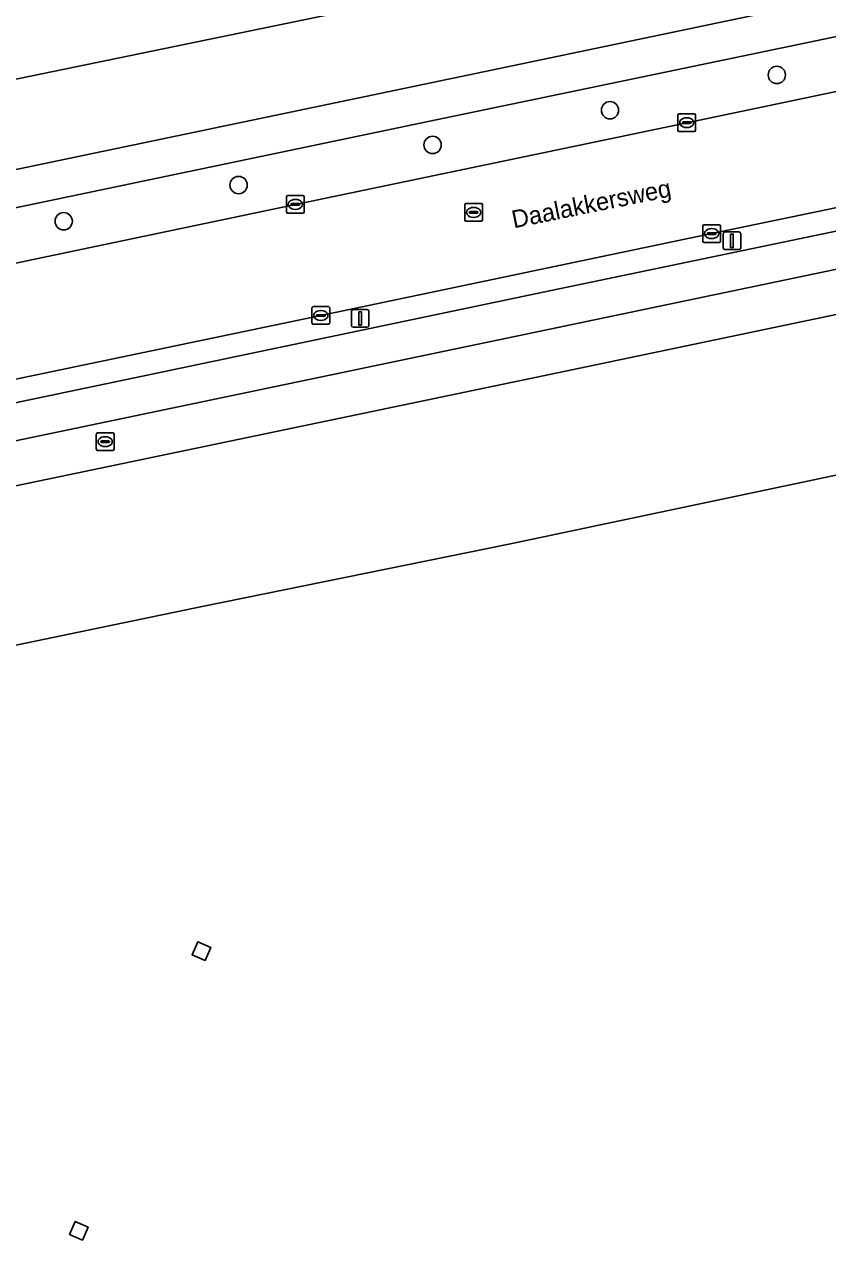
# Model space of a CAD drawing. Extents: x 164494 to 166241, y 382475 to 384495.
# Drawn here: x 165022 to 165067.4, y 384305.4 to 384374.5 of the extents above; entities that cross this region are included whole.
import ezdxf

# ---------------------------------------------------------------- set-up
doc = ezdxf.new("R2010")
doc.units = 0
for name, color, linetype in [('IMGEO_Berm_groen', 7, 'Continuous'), ('IMGEO_Boom', 7, 'Continuous'), ('IMGEO_Brandkraan', 7, 'Continuous'), ('IMGEO_Erf', 7, 'Continuous'), ('IMGEO_Fietspad_open', 7, 'Continuous'), ('IMGEO_Greppel_droge_sloot', 7, 'Continuous'), ('IMGEO_Groenvoorziening', 7, 'Continuous'), ('IMGEO_Hek', 7, 'Continuous'), ('IMGEO_Hoogspanningsmast', 7, 'Continuous'), ('IMGEO_Kolk', 7, 'Continuous'), ('IMGEO_Lichtmast', 7, 'Continuous'), ('IMGEO_Openbare_ruimte_label', 7, 'Continuous'), ('IMGEO_Rijbaan_lokaal_open', 7, 'Continuous'), ('IMGEO_Rioolput', 7, 'Continuous'), ('IMGEO_Struiken', 7, 'Continuous'), ('IMGEO_Voetpad_open', 7, 'Continuous')]:
    doc.layers.add(name, color=color, linetype=linetype)

msp = doc.modelspace()

# ---------------------------------------------------------------- linework, layer by layer
at = {"layer": 'IMGEO_Berm_groen'}
for points in [[(165103.145, 384381.247), (165078.417, 384376.067), (165044.842, 384369.066), (164998.737, 384359.434), (164936.708, 384346.52), (164925.461, 384344.192), (164926.103, 384341.106), (164933.216, 384342.574), (164954.306, 384347.035), (164980.37, 384352.43), (164994.137, 384355.385), (165015.253, 384359.737), (165037.346, 384364.383), (165059.459, 384368.999), (165082.552, 384373.828), (165103.18, 384378.131), (165103.841, 384378.298)], [(165118.108, 384374.601), (165083.93, 384367.513), (165060.866, 384362.734), (165038.786, 384358.11), (165016.662, 384353.497), (165001.186, 384350.268), (165001.461, 384348.974), (165051.79, 384359.513), (165100.699, 384369.712), (165114.768, 384372.637)]]:
    msp.add_lwpolyline(points, dxfattribs=at)
at = {"layer": 'IMGEO_Boom'}
for centre in [(165064.547, 384371.695), (165055.122, 384369.705), (165045.099, 384367.741), (165034.14, 384365.475), (165024.257, 384363.43)]:
    msp.add_circle(centre, 0.489, dxfattribs=at)
at = {"layer": 'IMGEO_Brandkraan'}
for p, q in [((165026.101, 384350.558), (165026.101, 384351.41)), ((165026.176, 384351.484), (165027.028, 384351.484)), ((165026.589, 384351.264), (165026.614, 384351.264)), ((165027.102, 384351.41), (165027.102, 384350.558)), ((165026.36, 384350.978), (165026.36, 384350.99)), ((165026.798, 384350.941), (165026.4, 384350.941)), ((165026.403, 384351.027), (165026.801, 384351.027)), ((165026.612, 384350.704), (165026.587, 384350.704)), ((165026.844, 384350.99), (165026.844, 384350.978)), ((165027.028, 384350.484), (165026.176, 384350.484))]:
    msp.add_line(p, q, dxfattribs=at)
for points in [[(165026.101, 384350.558), (165026.101, 384351.41)], [(165026.176, 384351.484), (165027.028, 384351.484)], [(165027.102, 384351.41), (165027.102, 384350.558)], [(165027.028, 384350.484), (165026.176, 384350.484)]]:
    msp.add_lwpolyline(points, dxfattribs=at)
for centre, radius, start, end in [((165026.178, 384351.408), 0.0765, 91.55205, 178.44795), ((165026.178, 384351.408), 0.0765, 91.55205, 178.44795), ((165027.026, 384351.408), 0.0765, 1.55205, 88.44795), ((165027.026, 384351.408), 0.0765, 1.55205, 88.44795), ((165026.4, 384350.987), 0.0403, 85.87752, 175.75265), ((165026.397, 384350.977), 0.0366, 178.93798, 274.71019), ((165026.801, 384350.984), 0.043, 264.86636, 352.45326), ((165026.805, 384350.989), 0.0386, 1.73085, 96.63898), ((165026.178, 384350.56), 0.0765, 181.55205, 268.44795), ((165026.178, 384350.56), 0.0765, 181.55205, 268.44795), ((165027.026, 384350.56), 0.0765, 271.55205, 358.44795), ((165027.026, 384350.56), 0.0765, 271.55205, 358.44795)]:
    msp.add_arc(centre, radius, start, end, dxfattribs=at)
for centre, major_axis, ratio, start_param, end_param in [((165026.588, 384350.984), (-0.387, 0.002), 0.722429, 4.712389, 7.853982), ((165026.613, 384350.984), (-0.39, 0.002), 0.717154, 1.570796, 4.712389)]:
    msp.add_ellipse(centre, major_axis=major_axis, ratio=ratio, start_param=start_param, end_param=end_param, dxfattribs=at)
at = {"layer": 'IMGEO_Erf'}
msp.add_lwpolyline([(165121.194, 384360.319), (165097.67, 384355.369), (165074.224, 384350.422), (165049.402, 384345.197), (165032.09, 384341.677), (165016.726, 384338.497)], dxfattribs=at)
for points in [[(165031.512, 384322.002), (165031.833, 384322.734), (165032.566, 384322.413), (165032.244, 384321.68)], [(165024.585, 384306.205), (165024.906, 384306.938), (165025.639, 384306.616), (165025.317, 384305.884)]]:
    msp.add_lwpolyline(points, close=True, dxfattribs=at)
at = {"layer": 'IMGEO_Fietspad_open'}
for points in [[(165106.766, 384384.165), (165105.349, 384383.872), (165102.387, 384383.258), (165077.784, 384378.116), (165043.832, 384371.007), (165000.08, 384361.873), (164984.803, 384358.696), (164934.915, 384348.321), (164898.89, 384340.836), (164875.602, 384335.981), (164845.275, 384329.624), (164797.88, 384319.828), (164794.806, 384319.188), (164795.6, 384317.184)], [(164795.6, 384317.184), (164798.561, 384317.801), (164845.552, 384327.536), (164876.06, 384333.902), (164900.22, 384338.981), (164917.673, 384342.602), (164918.341, 384339.504), (164926.103, 384341.106), (164925.461, 384344.192), (164936.708, 384346.52), (164998.737, 384359.434), (165044.842, 384369.066), (165078.417, 384376.067), (165103.145, 384381.247)], [(165118.509, 384373.384), (165114.768, 384372.637), (165100.699, 384369.712), (165051.79, 384359.513), (165001.461, 384348.974), (164996.183, 384347.859), (164980.371, 384344.544), (164956.926, 384339.68), (164933.359, 384334.783), (164911.059, 384330.145), (164868.55, 384321.331), (164832.678, 384313.85), (164825.97, 384312.501), (164814.364, 384310.101), (164814.35, 384310.172), (164809.331, 384309.126), (164809.333, 384309.08), (164801.696, 384307.495)], [(164802.068, 384305.407), (164809.925, 384307.04), (164833.08, 384311.822), (164838.611, 384312.969), (164868.92, 384319.253), (164912.329, 384328.255), (164932.507, 384332.46), (164958.923, 384337.938), (164978.743, 384342.085), (164996.584, 384345.814), (165001.876, 384346.919), (165052.181, 384357.436), (165101.155, 384367.679), (165118.614, 384371.278), (165123.59, 384372.323)]]:
    msp.add_lwpolyline(points, dxfattribs=at)
at = {"layer": 'IMGEO_Greppel_droge_sloot'}
msp.add_lwpolyline([(164862.281, 384339.951), (164950.027, 384358.074), (164983.603, 384364.664), (164999.896, 384367.862), (165017.437, 384370.613), (165038.566, 384374.957), (165060.537, 384379.313), (165104.508, 384388.354), (165104.993, 384388.454), (165106.065, 384389.82), (165106.003, 384390.697), (165105.583, 384391.703), (165104.253, 384391.797), (165094.853, 384389.829), (165092.786, 384389.521), (165090.64, 384389.08), (165088.711, 384388.988), (165086.738, 384389.38), (165085.335, 384389.341), (165083.775, 384389.121), (165040.998, 384380.02), (165000.91, 384371.603), (164912.198, 384353.222)], dxfattribs=at)
at = {"layer": 'IMGEO_Groenvoorziening'}
msp.add_lwpolyline([(165097.67, 384355.369), (165121.194, 384360.319), (165128.463, 384361.866), (165121.469, 384369.317), (165101.82, 384365.255), (165052.6, 384354.959), (165007.446, 384345.541), (165010.705, 384337.217), (165014.207, 384337.944), (165014.284, 384337.57), (165016.804, 384338.097), (165016.726, 384338.497), (165032.09, 384341.677), (165049.402, 384345.197), (165074.224, 384350.422)], close=True, dxfattribs=at)
at = {"layer": 'IMGEO_Hek'}
for points in [[(164792.371, 384325.328), (164793.82, 384325.659), (164799.547, 384326.819), (164862.281, 384339.951), (164950.027, 384358.074), (164999.896, 384367.862), (165017.437, 384370.613), (165038.566, 384374.957), (165060.537, 384379.313), (165104.993, 384388.454), (165107.365, 384388.949), (165107.179, 384392.936), (165107.536, 384394.767)], [(165128.694, 384361.62), (165128.463, 384361.866), (165121.194, 384360.319), (165097.67, 384355.369), (165074.224, 384350.422), (165049.402, 384345.197), (165032.09, 384341.677), (165016.726, 384338.497), (165016.804, 384338.097)]]:
    msp.add_lwpolyline(points, dxfattribs=at)
at = {"layer": 'IMGEO_Hoogspanningsmast'}
for points in [[(165031.833, 384322.734), (165031.512, 384322.002), (165032.244, 384321.68), (165032.566, 384322.413)], [(165024.585, 384306.205), (165025.317, 384305.884), (165025.639, 384306.616), (165024.906, 384306.938)]]:
    msp.add_lwpolyline(points, close=True, dxfattribs=at)
at = {"layer": 'IMGEO_Kolk'}
for p, q in [((165058.958, 384368.573), (165058.958, 384369.425)), ((165059.033, 384369.499), (165059.885, 384369.499)), ((165059.446, 384369.279), (165059.471, 384369.279)), ((165059.959, 384369.425), (165059.959, 384368.573)), ((165059.217, 384368.993), (165059.217, 384369.005)), ((165059.655, 384368.956), (165059.257, 384368.956)), ((165059.26, 384369.042), (165059.658, 384369.042)), ((165059.469, 384368.719), (165059.444, 384368.719)), ((165059.701, 384369.005), (165059.701, 384368.993)), ((165059.885, 384368.499), (165059.033, 384368.499)), ((165036.845, 384363.957), (165036.845, 384364.809)), ((165036.92, 384364.883), (165037.772, 384364.883)), ((165037.147, 384364.426), (165037.545, 384364.426)), ((165037.333, 384364.663), (165037.358, 384364.663)), ((165037.846, 384364.809), (165037.846, 384363.957)), ((165037.772, 384363.883), (165036.92, 384363.883)), ((165037.104, 384364.377), (165037.104, 384364.389)), ((165037.542, 384364.34), (165037.144, 384364.34)), ((165037.356, 384364.103), (165037.331, 384364.103)), ((165037.588, 384364.389), (165037.588, 384364.377)), ((165060.365, 384362.308), (165060.365, 384363.16)), ((165060.44, 384363.234), (165061.292, 384363.234)), ((165060.853, 384363.014), (165060.878, 384363.014)), ((165061.366, 384363.16), (165061.366, 384362.308)), ((165060.624, 384362.728), (165060.624, 384362.74)), ((165061.062, 384362.691), (165060.664, 384362.691)), ((165060.667, 384362.777), (165061.065, 384362.777)), ((165060.876, 384362.454), (165060.851, 384362.454)), ((165061.108, 384362.74), (165061.108, 384362.728)), ((165061.292, 384362.234), (165060.44, 384362.234)), ((165038.285, 384357.684), (165038.285, 384358.536)), ((165038.36, 384358.61), (165039.212, 384358.61)), ((165038.773, 384358.39), (165038.798, 384358.39)), ((165039.286, 384358.536), (165039.286, 384357.684)), ((165039.212, 384357.61), (165038.36, 384357.61)), ((165038.544, 384358.104), (165038.544, 384358.116)), ((165038.982, 384358.067), (165038.584, 384358.067)), ((165038.587, 384358.153), (165038.985, 384358.153)), ((165038.796, 384357.83), (165038.771, 384357.83)), ((165039.028, 384358.116), (165039.028, 384358.104))]:
    msp.add_line(p, q, dxfattribs=at)
for points in [[(165058.958, 384368.573), (165058.958, 384369.425)], [(165059.033, 384369.499), (165059.885, 384369.499)], [(165059.959, 384369.425), (165059.959, 384368.573)], [(165059.885, 384368.499), (165059.033, 384368.499)], [(165036.845, 384363.957), (165036.845, 384364.809)], [(165036.92, 384364.883), (165037.772, 384364.883)], [(165037.846, 384364.809), (165037.846, 384363.957)], [(165037.772, 384363.883), (165036.92, 384363.883)], [(165060.365, 384362.308), (165060.365, 384363.16)], [(165060.44, 384363.234), (165061.292, 384363.234)], [(165061.366, 384363.16), (165061.366, 384362.308)], [(165061.292, 384362.234), (165060.44, 384362.234)], [(165038.285, 384357.684), (165038.285, 384358.536)], [(165038.36, 384358.61), (165039.212, 384358.61)], [(165039.286, 384358.536), (165039.286, 384357.684)], [(165039.212, 384357.61), (165038.36, 384357.61)]]:
    msp.add_lwpolyline(points, dxfattribs=at)
for centre, radius, start, end in [((165059.035, 384369.423), 0.0765, 91.55205, 178.44795), ((165059.035, 384369.423), 0.0765, 91.55205, 178.44795), ((165059.883, 384369.423), 0.0765, 1.55205, 88.44795), ((165059.883, 384369.423), 0.0765, 1.55205, 88.44795), ((165059.035, 384368.575), 0.0765, 181.55205, 268.44795), ((165059.035, 384368.575), 0.0765, 181.55205, 268.44795), ((165059.257, 384369.002), 0.0403, 85.87752, 175.75265), ((165059.254, 384368.992), 0.0366, 178.93798, 274.71019), ((165059.658, 384368.999), 0.043, 264.86636, 352.45326), ((165059.662, 384369.004), 0.0386, 1.73085, 96.63898), ((165059.883, 384368.575), 0.0765, 271.55205, 358.44795), ((165059.883, 384368.575), 0.0765, 271.55205, 358.44795), ((165036.922, 384364.807), 0.0765, 91.55205, 178.44795), ((165036.922, 384364.807), 0.0765, 91.55205, 178.44795), ((165037.144, 384364.386), 0.0403, 85.87752, 175.75265), ((165037.549, 384364.388), 0.0386, 1.73085, 96.63898), ((165037.77, 384364.807), 0.0765, 1.55205, 88.44795), ((165037.77, 384364.807), 0.0765, 1.55205, 88.44795), ((165036.922, 384363.959), 0.0765, 181.55205, 268.44795), ((165036.922, 384363.959), 0.0765, 181.55205, 268.44795), ((165037.141, 384364.376), 0.0366, 178.93798, 274.71019), ((165037.545, 384364.383), 0.043, 264.86636, 352.45326), ((165037.77, 384363.959), 0.0765, 271.55205, 358.44795), ((165037.77, 384363.959), 0.0765, 271.55205, 358.44795), ((165060.442, 384363.158), 0.0765, 91.55205, 178.44795), ((165060.442, 384363.158), 0.0765, 91.55205, 178.44795), ((165061.29, 384363.158), 0.0765, 1.55205, 88.44795), ((165061.29, 384363.158), 0.0765, 1.55205, 88.44795), ((165060.664, 384362.737), 0.0403, 85.87752, 175.75265), ((165060.661, 384362.727), 0.0366, 178.93798, 274.71019), ((165061.065, 384362.734), 0.043, 264.86636, 352.45326), ((165061.069, 384362.739), 0.0386, 1.73085, 96.63898), ((165060.442, 384362.31), 0.0765, 181.55205, 268.44795), ((165060.442, 384362.31), 0.0765, 181.55205, 268.44795), ((165061.29, 384362.31), 0.0765, 271.55205, 358.44795), ((165061.29, 384362.31), 0.0765, 271.55205, 358.44795), ((165038.362, 384358.534), 0.0765, 91.55205, 178.44795), ((165038.362, 384358.534), 0.0765, 91.55205, 178.44795), ((165039.21, 384358.534), 0.0765, 1.55205, 88.44795), ((165039.21, 384358.534), 0.0765, 1.55205, 88.44795), ((165038.362, 384357.686), 0.0765, 181.55205, 268.44795), ((165038.362, 384357.686), 0.0765, 181.55205, 268.44795), ((165038.584, 384358.113), 0.0403, 85.87752, 175.75265), ((165038.581, 384358.103), 0.0366, 178.93798, 274.71019), ((165038.985, 384358.11), 0.043, 264.86636, 352.45326), ((165038.989, 384358.115), 0.0386, 1.73085, 96.63898), ((165039.21, 384357.686), 0.0765, 271.55205, 358.44795), ((165039.21, 384357.686), 0.0765, 271.55205, 358.44795)]:
    msp.add_arc(centre, radius, start, end, dxfattribs=at)
for centre, major_axis, ratio, start_param, end_param in [((165059.445, 384368.999), (-0.387, 0.002), 0.722429, 4.712389, 7.853982), ((165059.47, 384368.999), (-0.39, 0.002), 0.717154, 1.570796, 4.712389), ((165037.332, 384364.383), (-0.387, 0.002), 0.722429, 4.712389, 7.853982), ((165037.357, 384364.383), (-0.39, 0.002), 0.717154, 1.570796, 4.712389), ((165060.852, 384362.734), (-0.387, 0.002), 0.722429, 4.712389, 7.853982), ((165060.877, 384362.734), (-0.39, 0.002), 0.717154, 1.570796, 4.712389), ((165038.772, 384358.11), (-0.387, 0.002), 0.722429, 4.712389, 7.853982), ((165038.797, 384358.11), (-0.39, 0.002), 0.717154, 1.570796, 4.712389)]:
    msp.add_ellipse(centre, major_axis=major_axis, ratio=ratio, start_param=start_param, end_param=end_param, dxfattribs=at)
at = {"layer": 'IMGEO_Lichtmast'}
for p, q in [((165061.516, 384361.929), (165061.516, 384362.729)), ((165061.516, 384362.729), (165061.516, 384361.929)), ((165061.616, 384362.829), (165062.406, 384362.829)), ((165062.406, 384362.829), (165061.616, 384362.829)), ((165062.506, 384362.729), (165062.506, 384361.929)), ((165062.506, 384361.929), (165062.506, 384362.729)), ((165062.406, 384361.829), (165061.616, 384361.829)), ((165061.616, 384361.829), (165062.406, 384361.829)), ((165040.51, 384357.545), (165040.51, 384358.345)), ((165040.51, 384358.345), (165040.51, 384357.545)), ((165040.61, 384358.445), (165041.4, 384358.445)), ((165041.4, 384358.445), (165040.61, 384358.445)), ((165041.5, 384358.345), (165041.5, 384357.545)), ((165041.5, 384357.545), (165041.5, 384358.345)), ((165041.4, 384357.445), (165040.61, 384357.445)), ((165040.61, 384357.445), (165041.4, 384357.445))]:
    msp.add_line(p, q, dxfattribs=at)
for points in [[(165061.936, 384362.704), (165062.086, 384362.704), (165062.086, 384361.954), (165061.936, 384361.954), (165061.936, 384362.704)], [(165040.93, 384358.32), (165041.08, 384358.32), (165041.08, 384357.57), (165040.93, 384357.57), (165040.93, 384358.32)]]:
    msp.add_lwpolyline(points, dxfattribs=at)
for centre, start, end in [((165061.616, 384362.729), 90, 180), ((165061.616, 384362.729), 90, 180), ((165062.406, 384362.729), 0, 90), ((165062.406, 384362.729), 360, 90), ((165061.616, 384361.929), 180, 270), ((165061.616, 384361.929), 180, 270), ((165062.406, 384361.929), 270, 0), ((165062.406, 384361.929), 270, 0), ((165040.61, 384358.345), 90, 180), ((165040.61, 384358.345), 90, 180), ((165041.4, 384358.345), 0, 90), ((165041.4, 384358.345), 360, 90), ((165040.61, 384357.545), 180, 270), ((165040.61, 384357.545), 180, 270), ((165041.4, 384357.545), 270, 0), ((165041.4, 384357.545), 270, 0)]:
    msp.add_arc(centre, 0.1, start, end, dxfattribs=at)
at = {"layer": 'IMGEO_Rijbaan_lokaal_open'}
for points in [[(164923.017, 384333.971), (164933.937, 384336.234), (164935.002, 384336.455), (164955.553, 384340.732), (164955.712, 384340.765), (164981.397, 384346.103), (164981.482, 384346.121), (164995.659, 384349.115), (164995.895, 384349.164), (165001.186, 384350.268), (165016.662, 384353.497), (165038.786, 384358.11), (165060.866, 384362.734), (165083.93, 384367.513), (165118.108, 384374.601), (165110.316, 384389.55)], [(165103.841, 384378.298), (165103.18, 384378.131), (165082.552, 384373.828), (165059.459, 384368.999), (165037.346, 384364.383), (165015.253, 384359.737), (164994.137, 384355.385), (164980.37, 384352.43), (164954.306, 384347.035), (164933.216, 384342.574), (164926.103, 384341.106), (164918.341, 384339.504), (164908.242, 384337.42), (164886.155, 384332.862), (164865.073, 384328.486), (164845.934, 384324.502), (164823.887, 384319.91), (164800.79, 384315.134), (164796.746, 384314.295), (164799.153, 384308.224)]]:
    msp.add_lwpolyline(points, dxfattribs=at)
at = {"layer": 'IMGEO_Rioolput'}
for p, q in [((165046.993, 384364.431), (165047.845, 384364.431)), ((165046.918, 384363.505), (165046.918, 384364.357)), ((165047.177, 384363.925), (165047.177, 384363.937)), ((165047.615, 384363.888), (165047.217, 384363.888)), ((165047.22, 384363.974), (165047.618, 384363.974)), ((165047.406, 384364.211), (165047.431, 384364.211)), ((165047.661, 384363.937), (165047.661, 384363.925)), ((165047.919, 384364.357), (165047.919, 384363.505)), ((165047.845, 384363.431), (165046.993, 384363.431)), ((165047.429, 384363.651), (165047.404, 384363.651))]:
    msp.add_line(p, q, dxfattribs=at)
for points in [[(165046.993, 384364.431), (165047.845, 384364.431)], [(165046.918, 384363.505), (165046.918, 384364.357)], [(165047.919, 384364.357), (165047.919, 384363.505)], [(165047.845, 384363.431), (165046.993, 384363.431)]]:
    msp.add_lwpolyline(points, dxfattribs=at)
for centre, radius, start, end in [((165046.995, 384364.355), 0.0765, 91.55205, 178.44795), ((165046.995, 384364.355), 0.0765, 91.55205, 178.44795), ((165047.843, 384364.355), 0.0765, 1.55205, 88.44795), ((165047.843, 384364.355), 0.0765, 1.55205, 88.44795), ((165047.217, 384363.934), 0.0403, 85.87752, 175.75265), ((165047.214, 384363.924), 0.0366, 178.93798, 274.71019), ((165047.618, 384363.931), 0.043, 264.86636, 352.45326), ((165047.622, 384363.936), 0.0386, 1.73085, 96.63898), ((165046.995, 384363.507), 0.0765, 181.55205, 268.44795), ((165046.995, 384363.507), 0.0765, 181.55205, 268.44795), ((165047.843, 384363.507), 0.0765, 271.55205, 358.44795), ((165047.843, 384363.507), 0.0765, 271.55205, 358.44795)]:
    msp.add_arc(centre, radius, start, end, dxfattribs=at)
for centre, major_axis, ratio, start_param, end_param in [((165047.405, 384363.931), (-0.387, 0.002), 0.722429, 4.712389, 7.853982), ((165047.43, 384363.931), (-0.39, 0.002), 0.717154, 1.570796, 4.712389)]:
    msp.add_ellipse(centre, major_axis=major_axis, ratio=ratio, start_param=start_param, end_param=end_param, dxfattribs=at)
at = {"layer": 'IMGEO_Struiken'}
msp.add_lwpolyline([(165105.349, 384383.872), (165104.508, 384388.354), (165060.537, 384379.313), (165038.566, 384374.957), (165017.437, 384370.613), (164999.896, 384367.862), (164983.603, 384364.664), (164984.803, 384358.696), (165000.08, 384361.873), (165043.832, 384371.007), (165077.784, 384378.116), (165102.387, 384383.258)], close=True, dxfattribs=at)
at = {"layer": 'IMGEO_Voetpad_open'}
for points in [[(165123.59, 384372.323), (165118.614, 384371.278), (165101.155, 384367.679), (165052.181, 384357.436), (165001.876, 384346.919), (164996.584, 384345.814), (164978.743, 384342.085), (164958.923, 384337.938), (164932.507, 384332.46), (164912.329, 384328.255), (164868.92, 384319.253), (164838.611, 384312.969), (164833.08, 384311.822), (164809.925, 384307.04), (164802.068, 384305.407)], [(164913.849, 384326.017), (164931.494, 384329.683), (164931.595, 384329.704), (164960.93, 384335.824), (164961.279, 384335.897), (164976.708, 384339.106), (164976.791, 384339.123), (164985.728, 384340.992), (164986.639, 384341.182), (164997.097, 384343.369), (164998.345, 384343.632), (165002.371, 384344.482), (165003.041, 384344.622), (165006.564, 384345.357), (165007.446, 384345.541), (165052.6, 384354.959), (165101.82, 384365.255), (165121.469, 384369.317)]]:
    msp.add_lwpolyline(points, dxfattribs=at)

# ---------------------------------------------------------------- texts
at = {"layer": 'IMGEO_Openbare_ruimte_label'}
msp.add_text('Daalakkersweg', height=1, rotation=11.42232, dxfattribs=at).set_placement((165049.682, 384363.03))

doc.saveas('drawing.dxf')
